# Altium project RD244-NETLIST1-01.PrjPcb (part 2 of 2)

## Sheet 6.SchDoc
size 609 x 444 mm
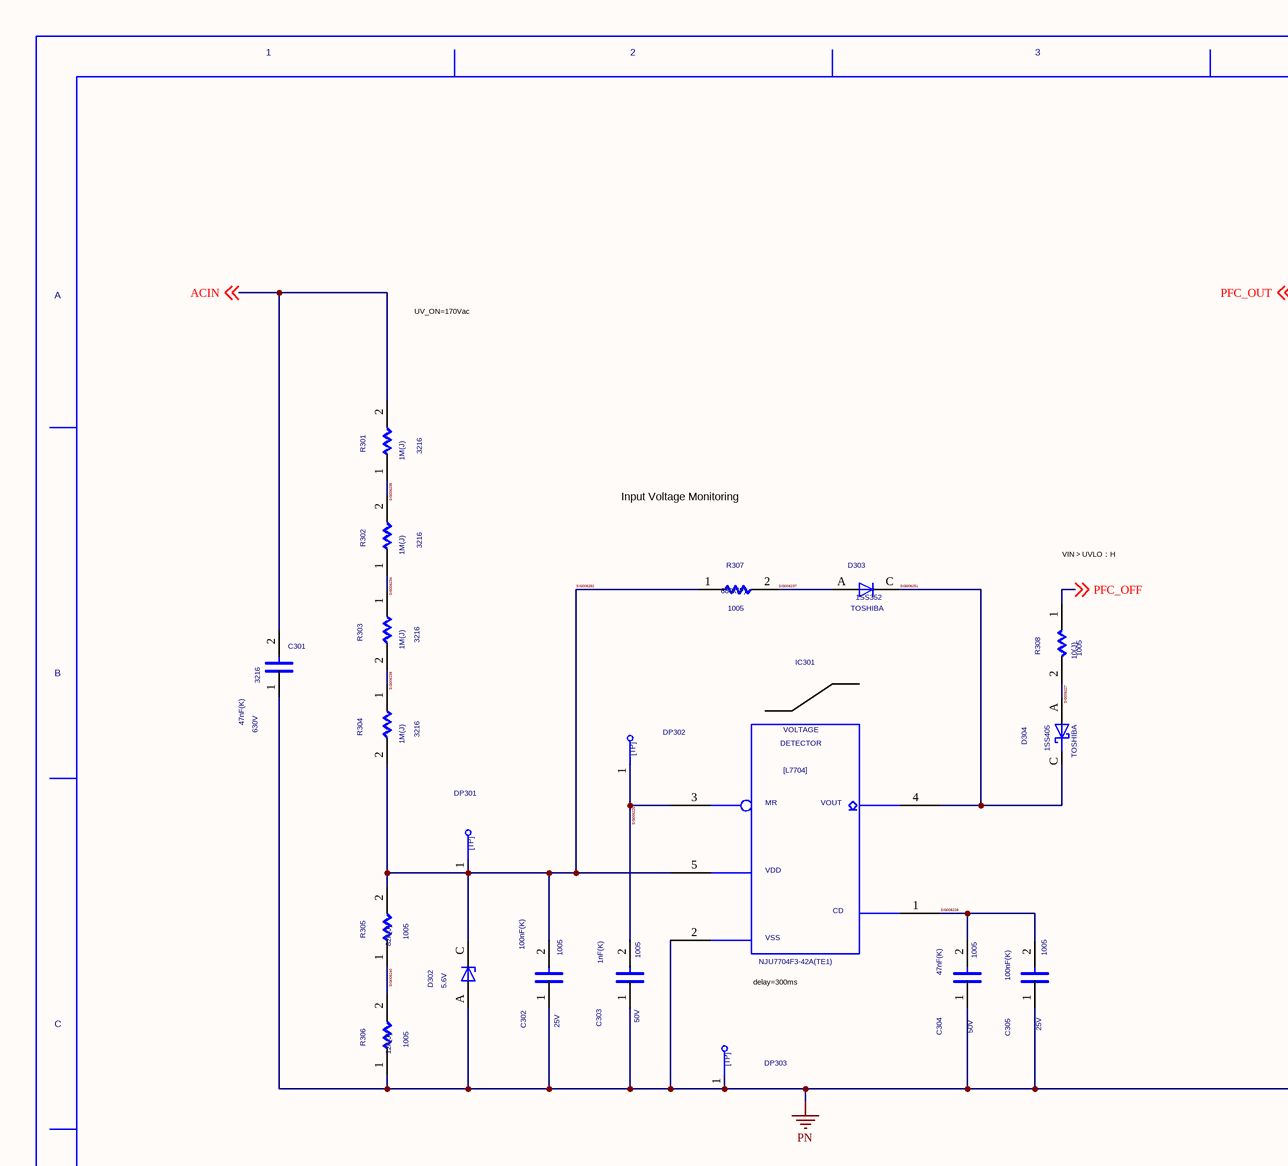
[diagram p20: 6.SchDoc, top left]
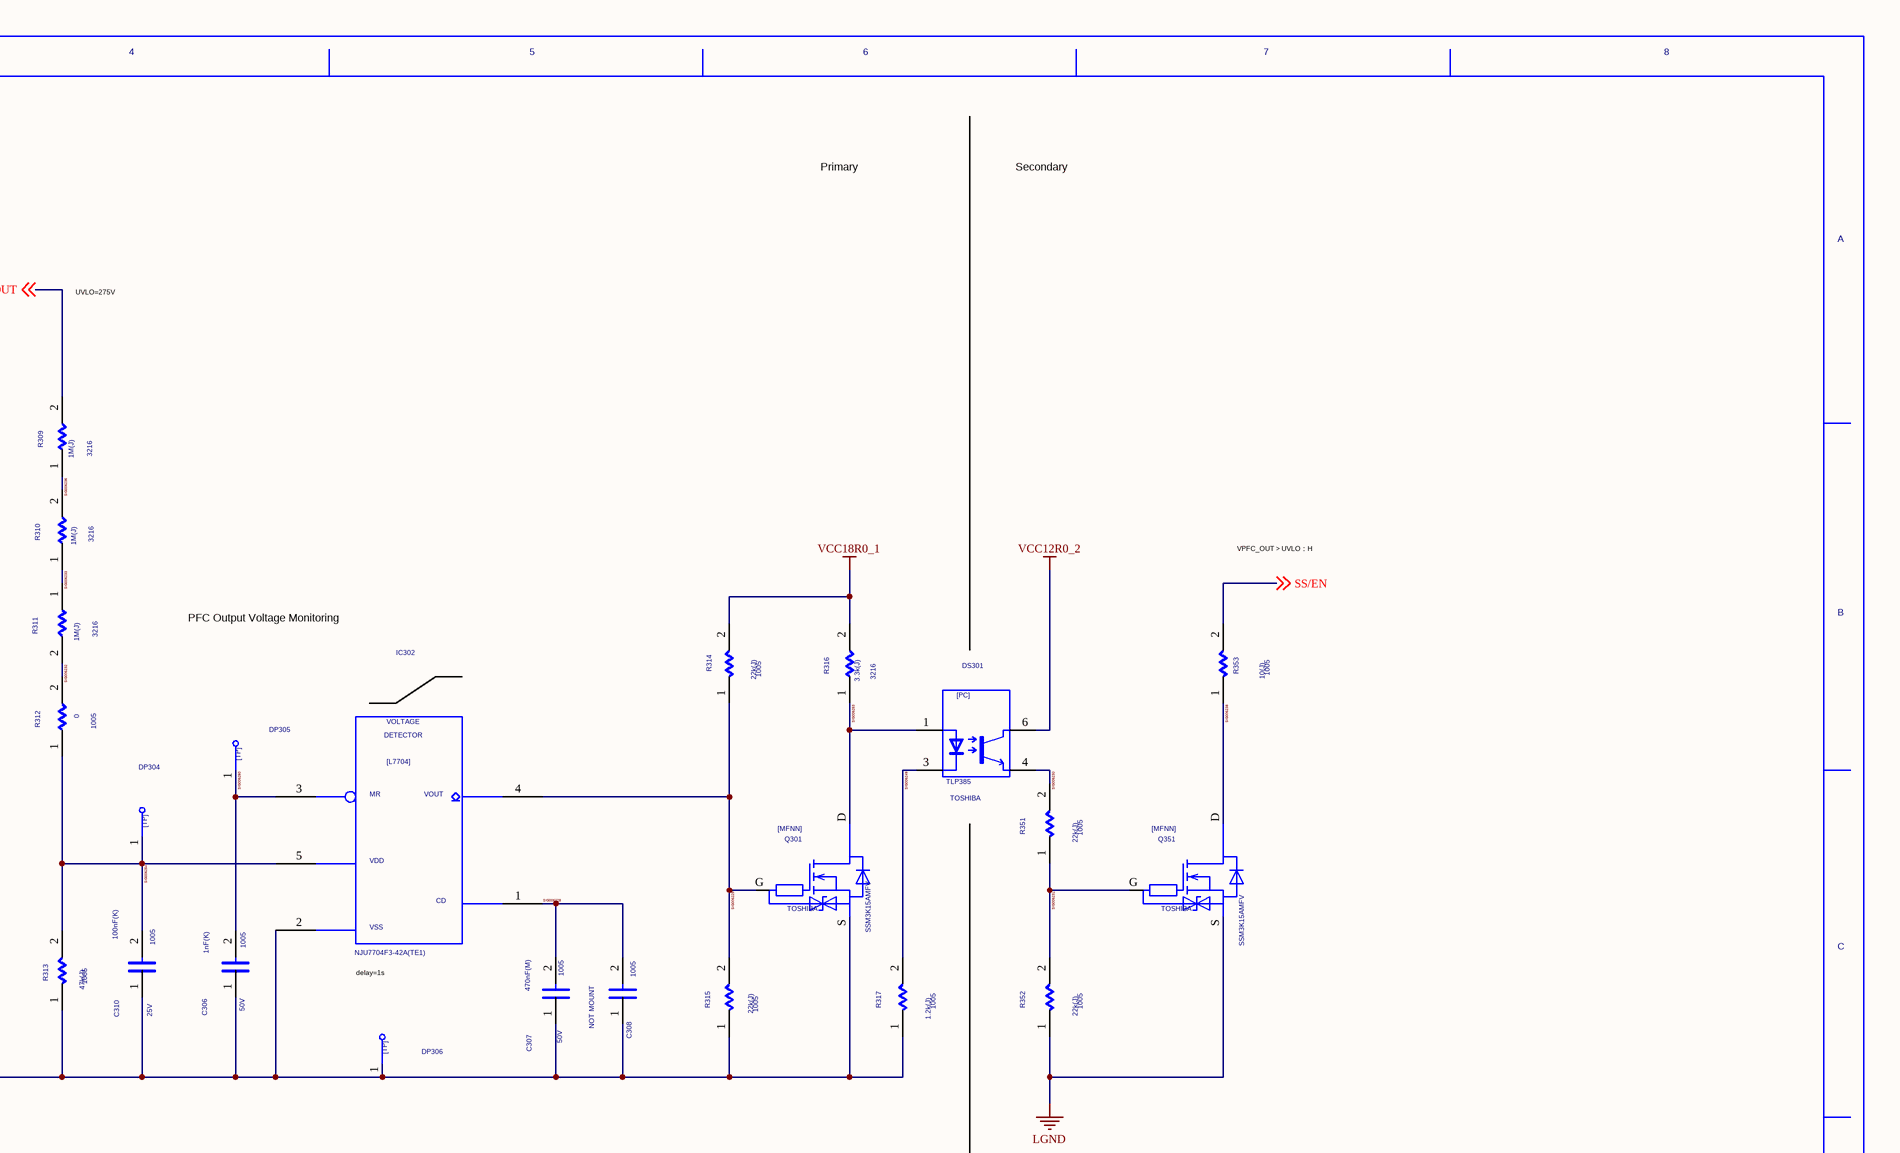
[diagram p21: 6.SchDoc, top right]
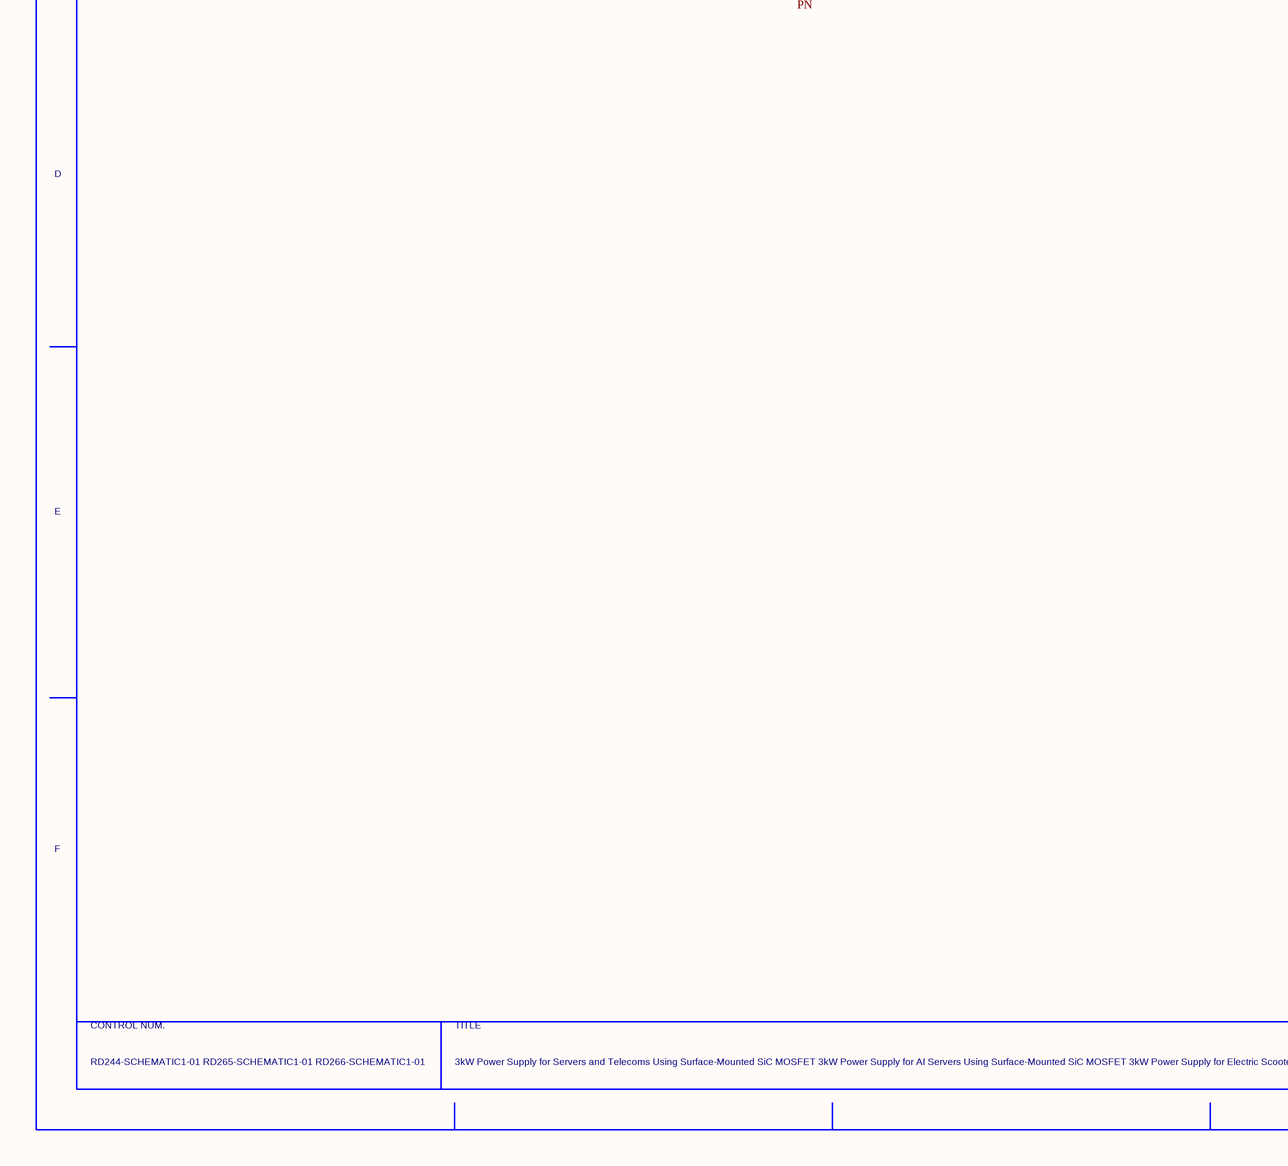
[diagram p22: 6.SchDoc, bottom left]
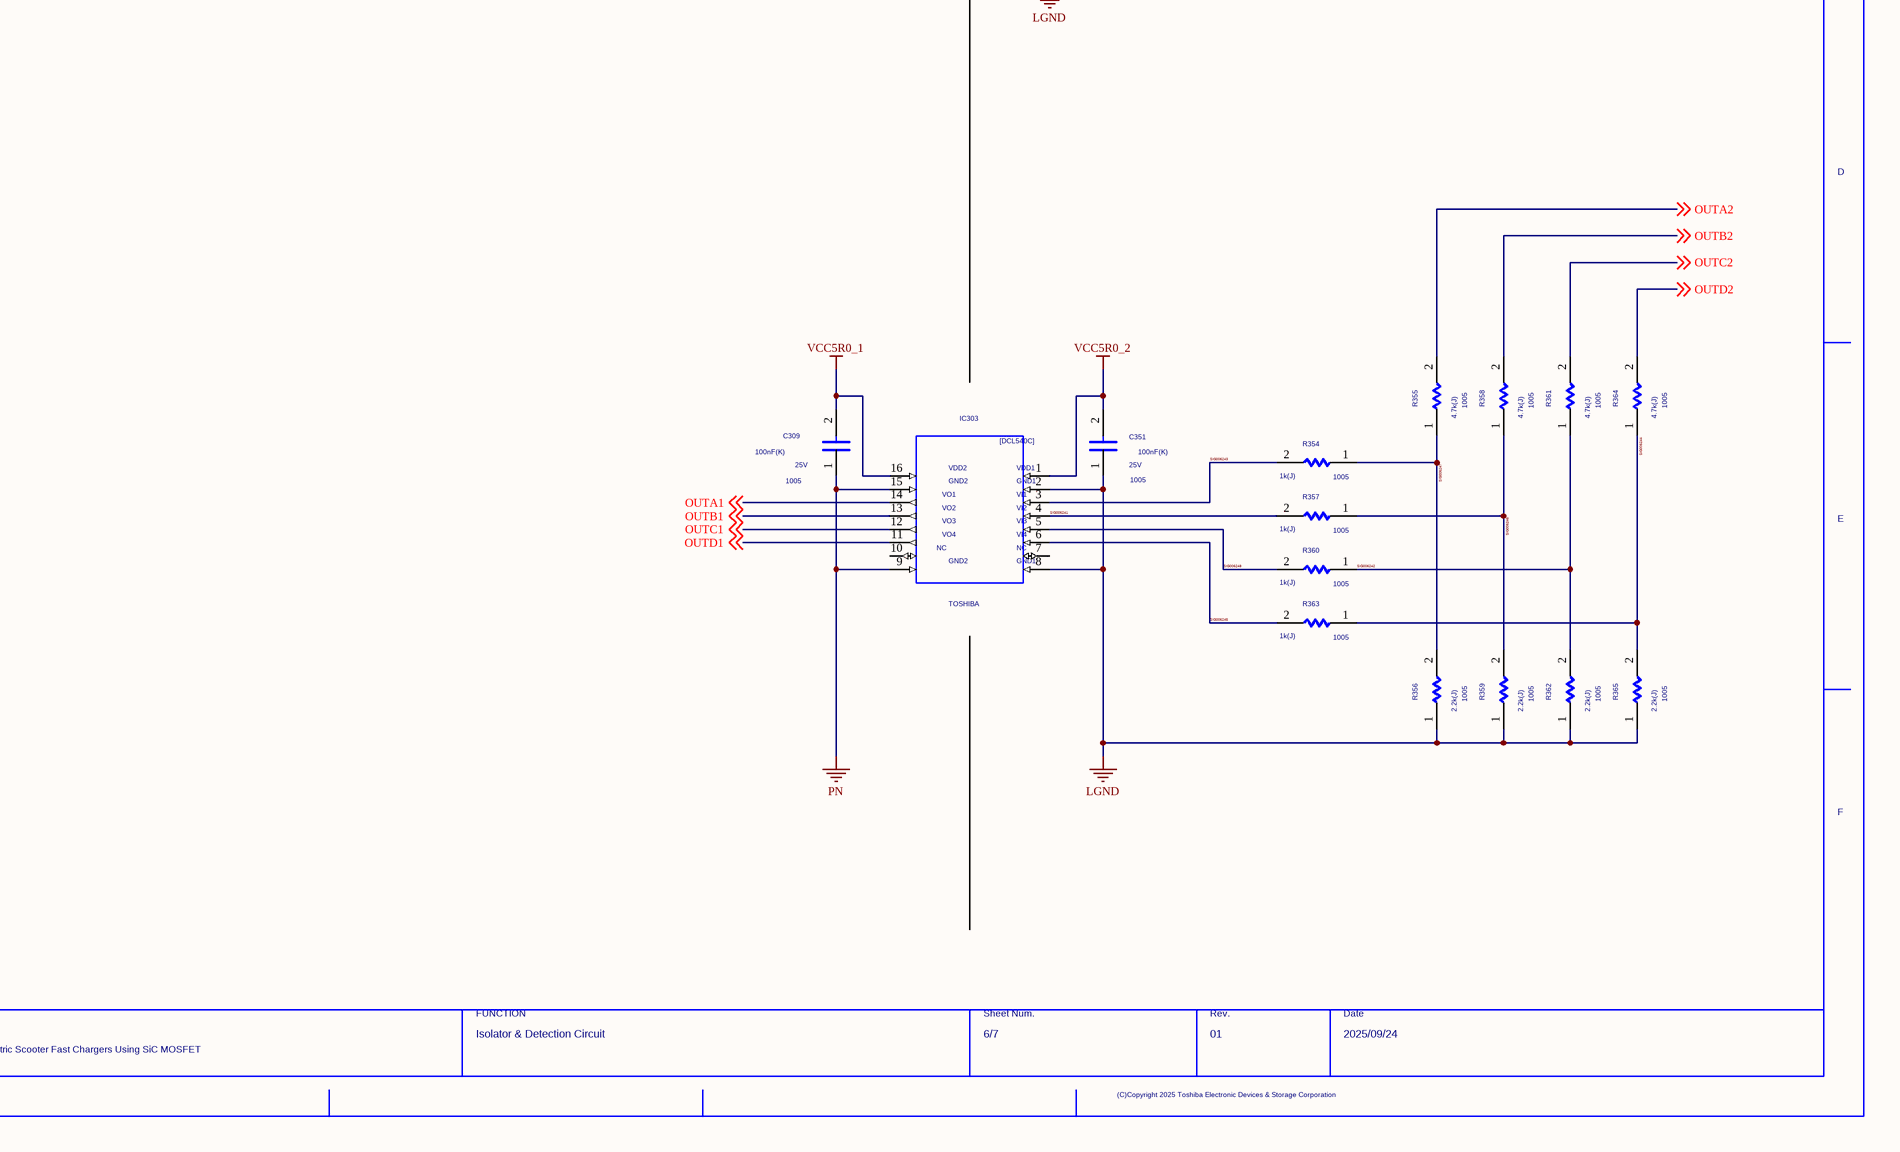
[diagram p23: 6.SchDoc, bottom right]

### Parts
(Parts that share a designator on the sheet are numbered #1, #2 ... from top to bottom, then left to right.)
C301  VAL1: 47nF(K)  VAL2: 630V  SIZECODESMD: 3216  (hidden comment: C)
C302  VAL1: 100nF(K)  VAL2: 25V  SIZECODESMD: 1005  (hidden comment: C)
C303  VAL1: 1nF(K)  VAL2: 50V  SIZECODESMD: 1005  (hidden comment: C)
C304  VAL1: 47nF(K)  VAL2: 50V  SIZECODESMD: 1005  (hidden comment: C)
C305  VAL1: 100nF(K)  VAL2: 25V  SIZECODESMD: 1005  (hidden comment: C)
C306  VAL1: 1nF(K)  VAL2: 50V  SIZECODESMD: 1005  (hidden comment: C)
C307  VAL1: 470nF(M)  VAL2: 50V  SIZECODESMD: 1005  (hidden comment: C)
C308  NOTMOUNT: NOT MOUNT  SIZECODESMD: 1005  (hidden comment: C)
C309  VAL1: 100nF(K)  VAL2: 25V  SIZECODESMD: 1005  (hidden comment: C)
C310  VAL1: 100nF(K)  VAL2: 25V  SIZECODESMD: 1005  (hidden comment: C)
C351  VAL1: 100nF(K)  VAL2: 25V  SIZECODESMD: 1005  (hidden comment: C)
D302  VAL1: 5.6V  (hidden comment: ZenerDiode_USC-01)
D303  USERCOMPTEXT3: TOSHIBA  VAL3: 1SS352  (hidden comment: D)
D304  USERCOMPTEXT3: TOSHIBA  (hidden comment: 1SS405)
DP301  TP  (value not drawn)
DP302  TP  (value not drawn)
DP303  TP  (value not drawn)
DP304  TP  (value not drawn)
DP305  TP  (value not drawn)
DP306  TP  (value not drawn)
DS301  USERCOMPTEXT3: TOSHIBA  (hidden comment: TLP385)
IC301  VAL3: NJU7704F3-42A(TE1)  (hidden comment: L7704)
IC302  VAL3: NJU7704F3-42A(TE1)  (hidden comment: L7704)
IC303  USERCOMPTEXT3: TOSHIBA  (hidden comment: DCL540C01)
Q301  USERCOMPTEXT3: TOSHIBA  VAL3: SSM3K15AMFV  (hidden comment: MFNN)
Q351  USERCOMPTEXT3: TOSHIBA  VAL3: SSM3K15AMFV  (hidden comment: MFNN)
R301  VAL1: 1M(J)  SIZECODESMD: 3216  (hidden comment: R)
R302  VAL1: 1M(J)  SIZECODESMD: 3216  (hidden comment: R)
R303  VAL1: 1M(J)  SIZECODESMD: 3216  (hidden comment: R)
R304  VAL1: 1M(J)  SIZECODESMD: 3216  (hidden comment: R)
R305  VAL1: 82k(J)  SIZECODESMD: 1005  (hidden comment: R)
R306  VAL1: 12k(J)  SIZECODESMD: 1005  (hidden comment: R)
R307  VAL1: 680k(F)  SIZECODESMD: 1005  (hidden comment: R)
R308  VAL1: 10(J)  SIZECODESMD: 1005  (hidden comment: R)
R309  VAL1: 1M(J)  SIZECODESMD: 3216  (hidden comment: R)
R310  VAL1: 1M(J)  SIZECODESMD: 3216  (hidden comment: R)
R311  VAL1: 1M(J)  SIZECODESMD: 3216  (hidden comment: R)
R312  VAL1: 0  SIZECODESMD: 1005  (hidden comment: R)
R313  VAL1: 47k(J)  SIZECODESMD: 1005  (hidden comment: R)
R314  VAL1: 22k(J)  SIZECODESMD: 1005  (hidden comment: R)
R315  VAL1: 22k(J)  SIZECODESMD: 1005  (hidden comment: R)
R316  VAL1: 3.3k(J)  SIZECODESMD: 3216  (hidden comment: R)
R317  VAL1: 1.2k(J)  SIZECODESMD: 1005  (hidden comment: R)
R351  VAL1: 22k(J)  SIZECODESMD: 1005  (hidden comment: R)
R352  VAL1: 22k(J)  SIZECODESMD: 1005  (hidden comment: R)
R353  VAL1: 10(J)  SIZECODESMD: 1005  (hidden comment: R)
R354  VAL1: 1k(J)  SIZECODESMD: 1005  (hidden comment: R)
R355  VAL1: 4.7k(J)  SIZECODESMD: 1005  (hidden comment: R)
R356  VAL1: 2.2k(J)  SIZECODESMD: 1005  (hidden comment: R)
R357  VAL1: 1k(J)  SIZECODESMD: 1005  (hidden comment: R)
R358  VAL1: 4.7k(J)  SIZECODESMD: 1005  (hidden comment: R)
R359  VAL1: 2.2k(J)  SIZECODESMD: 1005  (hidden comment: R)
R360  VAL1: 1k(J)  SIZECODESMD: 1005  (hidden comment: R)
R361  VAL1: 4.7k(J)  SIZECODESMD: 1005  (hidden comment: R)
R362  VAL1: 2.2k(J)  SIZECODESMD: 1005  (hidden comment: R)
R363  VAL1: 1k(J)  SIZECODESMD: 1005  (hidden comment: R)
R364  VAL1: 4.7k(J)  SIZECODESMD: 1005  (hidden comment: R)
R365  VAL1: 2.2k(J)  SIZECODESMD: 1005  (hidden comment: R)
U?#6  DATE: 2025/09/24  DRAWINGNUMBER: RD244-SCHEMATIC1-01 / RD265-SCHEMATIC1-01 / RD266-SCHEMATIC1-01  TITLE: 3kW Power Supply for Servers and Telecoms Using Surface-Mounted SiC MOSFET / 3kW Power Supply for AI Servers Using Surface-Mounted SiC MOSFET / 3kW Power Supply for Electric Scooter Fast Chargers Using SiC MOSFET  FUNCTION: Isolator & Detection Circuit  SHEETNUMBER: 6/7  REVISION: 01  (hidden comment: WAKU_DEF_A3_1)

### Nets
LGND: C351.1 IC303.2 IC303.8 Q351.S R352.1 R356.1 R359.1 R362.1 R365.1
PN: C301.1 C302.1 C303.1 C304.1 C305.1 C306.1 C307.1 C308.1 C309.1 C310.1 D302.A DP303.1 DP306.1 IC301.2 IC302.2 IC303.9 IC303.15 Q301.S R306.1 R313.1 R315.1 R317.1
VCC5R0_1: C309.2 IC303.16
VCC5R0_2: C351.2 IC303.1
VCC12R0_2: DS301.6
VCC18R0_1: R314.2 R316.2
ACIN: C301.2 R301.2 ; off-sheet ACIN
OUTA1: IC303.14 ; off-sheet OUTA1
OUTA2: R355.2 ; off-sheet OUTA2
OUTB1: IC303.13 ; off-sheet OUTB1
OUTB2: R358.2 ; off-sheet OUTB2
OUTC1: IC303.12 ; off-sheet OUTC1
OUTC2: R361.2 ; off-sheet OUTC2
OUTD1: IC303.11 ; off-sheet OUTD1
OUTD2: R364.2 ; off-sheet OUTD2
PFC_OFF: R308.1 ; off-sheet PFC_OFF
PFC_OUT: R309.2 ; off-sheet PFC_OUT
SIG006225: C303.2 DP302.1 IC301.3
SIG006226: C304.2 C305.2 IC301.1
SIG006227: D304.A R308.2
SIG006228: C307.2 C308.2 IC302.1
SIG006229: IC302.4 Q301.G R314.1 R315.2
SIG006230: DS301.4 R351.2
SIG006231: Q351.G R351.1 R352.2
SIG006232: R311.2 R312.2
SIG006233: R310.1 R311.1
SIG006234: R302.1 R303.1
SIG006235: R301.1 R302.2
SIG006236: R309.1 R310.2
SIG006237: D303.A R307.2
SIG006238: Q351.D R353.1
SIG006239: R303.2 R304.1
SIG006240: R305.1 R306.2
SIG006241: IC303.4 R357.2
SIG006242: R360.1 R361.1 R362.2
SIG006243: IC303.3 R354.2
SIG006244: R363.1 R364.1 R365.2
SIG006245: IC303.6 R363.2
SIG006246: R357.1 R358.1 R359.2
SIG006247: R354.1 R355.1 R356.2
SIG006248: IC303.5 R360.2
SIG006249: DS301.3 R317.2
SIG006250: C306.2 DP305.1 IC302.3
SIG006251: D303.C D304.C IC301.4
SIG006252: C302.2 D302.C DP301.1 IC301.5 R304.2 R305.2 R307.1
SIG006253: DS301.1 Q301.D R316.1
SIG006254: C310.2 DP304.1 IC302.5 R312.1 R313.2
SS/EN: R353.2 ; off-sheet SS/EN

Not connected (* = marked no-connect by the designer): IC303 7 10

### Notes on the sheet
- Primary
- Secondary
- UV_ON=170Vac
  UV_OFF=158Vac
- UVLO=275V
- Input Voltage Monitoring
- VIN＞UVLO：H
  VIN＜UVLO：L
- VPFC_OUT＞UVLO：H
  VPFC_OUT＜UVLO：L
- PFC Output Voltage Monitoring
- (near IC301) delay=300ms
- (near IC302) delay=1s

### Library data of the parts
C301 = C_Dup2: OriginalSymbolOrigin: (2540,7620); COMP: PRT_46; MAXGCOUNT: 1; SAVECOUNT: 0
C302 C305 C309 C310 C351 = C_Dup2: SQ_PART_MODEL: CON_100N; OriginalSymbolOrigin: (2540,7620); COMP: PRT_52; MAXGCOUNT: 1; ADSCNVFLAG: ON; ADSCOMPONENTNAME: C_1005; SAVECOUNT: 0
C303 C304 C306 C307 = C_Dup2: OriginalSymbolOrigin: (2540,7620); COMP: PRT_52; MAXGCOUNT: 1; SAVECOUNT: 0
C308 = C_Dup2: VAL1: 10nF(K); VAL2: 50V; OriginalSymbolOrigin: (2540,7620); COMP: PRT_52; MAXGCOUNT: 1; SAVECOUNT: 0
D302 = ZENERDIODE_USC-01: SAVEAREA0: -4630,-153,17114,13055; TIME: 14:49:55; UPDATEUSER: t4887876; UPDATETIME: 08:23:49; SAVECOUNT: 9; OriginalSymbolOrigin: (5080,5080); MAXGCOUNT: 1; ADSCNVFLAG: ON; ADSCOMPONENTNAME: D_ZD; VAL3: XCUZ5V6
D303 = D_Dup1: SAVEAREA0: -225,-91,12804,7836; SAVECOUNT: 3; TIME: 14:49:55; UPDATEUSER: 19870035; UPDATETIME: 14:20:16; VAL1: 1SS352(TPH3,F); OriginalSymbolOrigin: (5080,5080); USERCOMPTEXT2: 80V,0.1A; COMP: PRT_27
D304 = 1SS405: SAVEAREA0: -4630,-153,17114,13055; TIME: 14:49:55; UPDATEUSER: t4887876; UPDATETIME: 11:25:22; SAVECOUNT: 16; CHIPSET: SOD-523; VAL1: 20V; VAL2: 0.05A; OriginalSymbolOrigin: (5080,5080); MAXGCOUNT: 1; ADSCNVFLAG: ON; ADSCOMPONENTNAME: D_SBD
DP301-DP306 = TP: TIME: 16:12:21; UPDATEUSER: fukuda-y; UPDATETIME: 16:18:11; SAVECOUNT: 2; SAVEAREA0: -242,-92,12810,7836; OriginalSymbolOrigin: (0,7620); USERCOMPTEXT1: Φ1.5mm; COMP: DTP815
DS301 = TLP385: TIME: 18:37:26; UPDATEUSER: t4887876; UPDATETIME: 18:41:04; SAVECOUNT: 3; OriginalSymbolOrigin: (5080,17780); GATENO: 1; ADSCNVFLAG: ON
IC301 IC302 = L7704: SAVECOUNT: 23; SAVEAREA0: -14253,-557,65080,48696; TIME: 18:10:57; UPDATEUSER: 19990028; UPDATETIME: 10:41:32; OriginalSymbolOrigin: (7620,45720); MAXGCOUNT: 1; COMP: GDM470001845; ADSCNVFLAG: ON; VAL1: NJU7704F3-25A(TE1); FUNCTION: OTHER
IC303 = DCL540C01: TIME: 11:12:35; UPDATEUSER: t6860224; UPDATETIME: 18:45:42; SAVECOUNT: 6; SAVEAREA0: -81052,-32740,106905,52903; OriginalSymbolOrigin: (5080,27940); MAXGCOUNT: 1; FUNCTION: FXD
Q301 Q351 = MFNN: SAVECOUNT: 25; SAVEAREA0: -2884,-274,25430,18334; TIME: 08:01:03; UPDATEUSER: sato-yr; UPDATETIME: 13:42:20; VAL1: SSM3K15AMFV,L3F(T; OriginalSymbolOrigin: (2540,17780); MAXGCOUNT: 1; COMP: GDM410000663; ADSCNVFLAG: ON; ADSCOMPONENTNAME: Q_MFNN
R301-R304 R309-R311 = R_Dup2: VAL2: 250mW; OriginalSymbolOrigin: (5080,5080); COMP: PRT_5; CHIPSIZE: 1608; MAXGCOUNT: 1; SAVECOUNT: 0
R305-R308 R313-R315 R317 R351-R365 = R_Dup2: VAL2: 63mW; OriginalSymbolOrigin: (5080,5080); COMP: GDM010004481; CHIPSIZE: 1608; MAXGCOUNT: 1; SAVECOUNT: 0
R312 = R_Dup2: VAL2: 63mW; OriginalSymbolOrigin: (5080,5080); MAXGCOUNT: 1; COMP: GDM010004481; CHIPSIZE: 1608
R316 = R_Dup2: SQ_PART_MODEL: RES_4.87K; VAL2: 250mW; OriginalSymbolOrigin: (5080,5080); COMP: PRT_5; CHIPSIZE: 1608; MAXGCOUNT: 1; ADSCNVFLAG: ON; ADSCOMPONENTNAME: R_3216; SAVECOUNT: 0
U?#6 = WAKU_DEF_A3_1: PLOTTIME: HH:MM; SAVEAREA0: 96913,-567914,509243,-368858; TIME: 16:14:05; UPDATEUSER: t5459927; UPDATETIME: 13:12:48; SAVECOUNT: 3; ZONEOFFSETX: 36; ZONEOFFSETY: -24; OriginalSymbolOrigin: (12700,-12700); SHTSAVECOUNT: 262; PAGENUMBER: 6; DESIGNED: TOSHIBA

## Sheet 7.SchDoc
size 609 x 444 mm
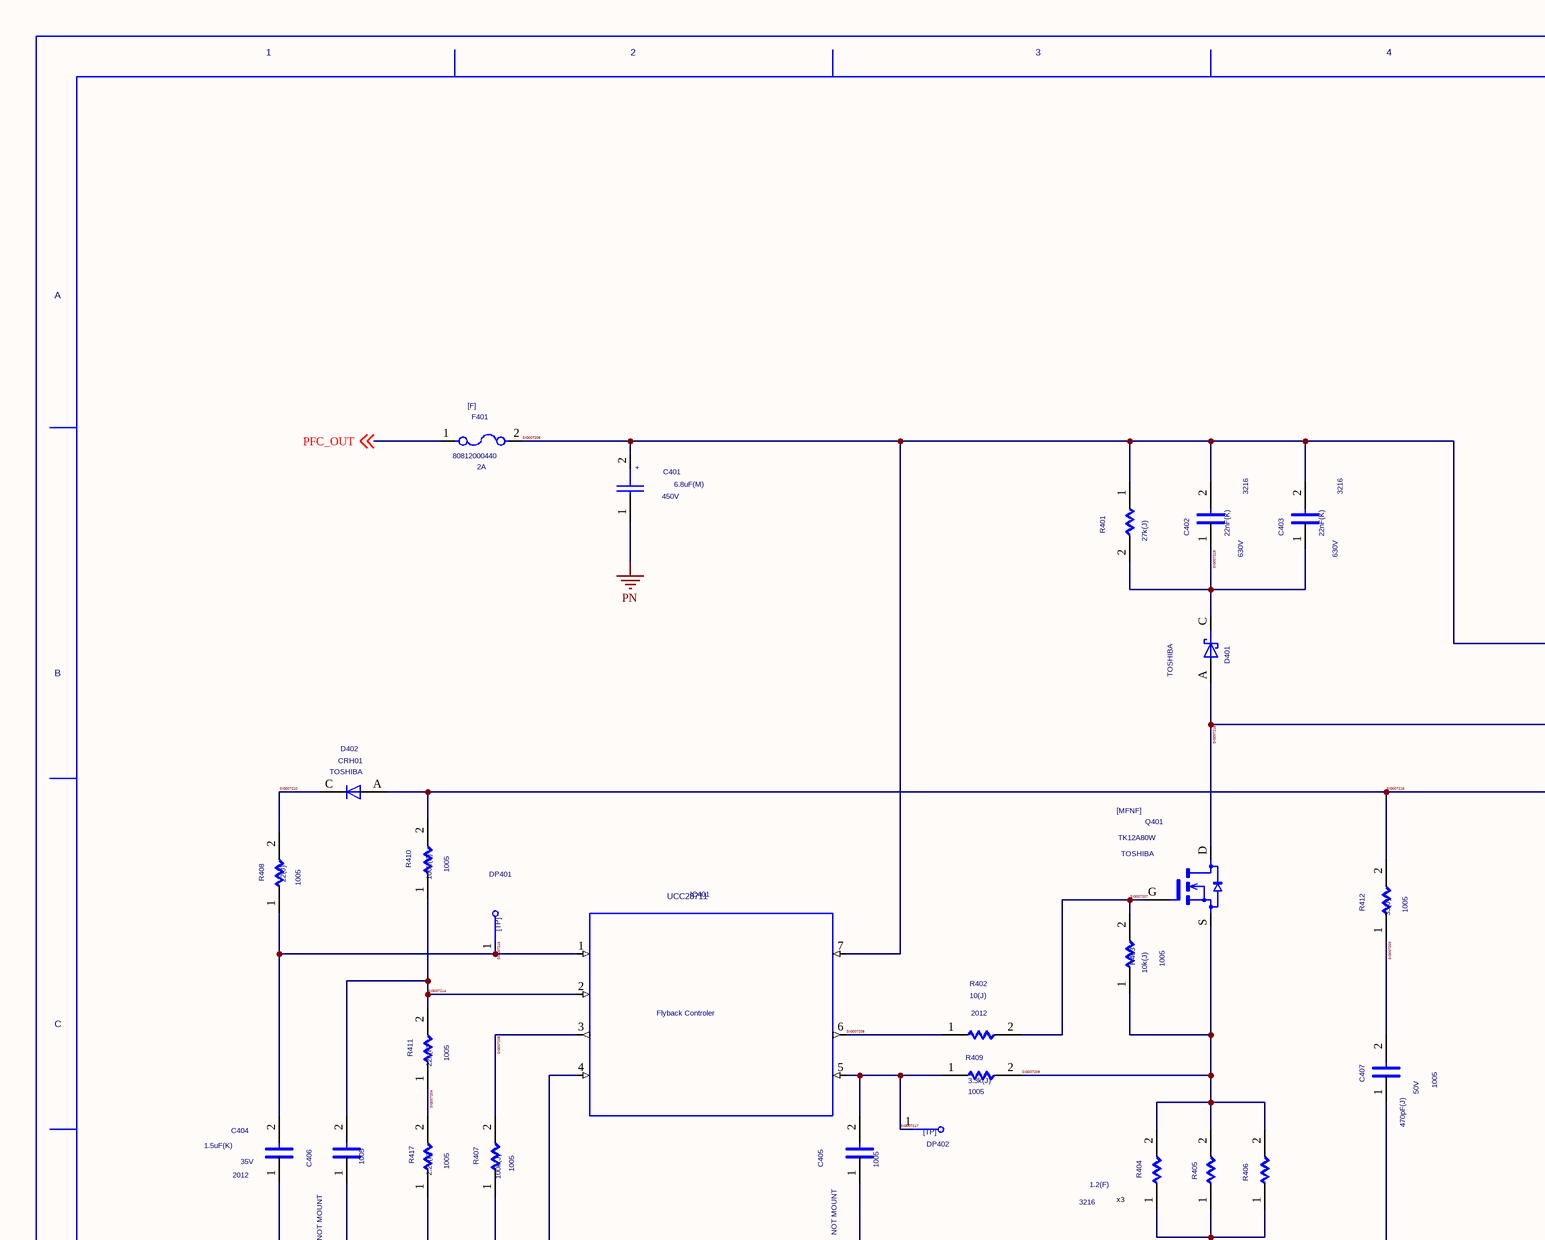
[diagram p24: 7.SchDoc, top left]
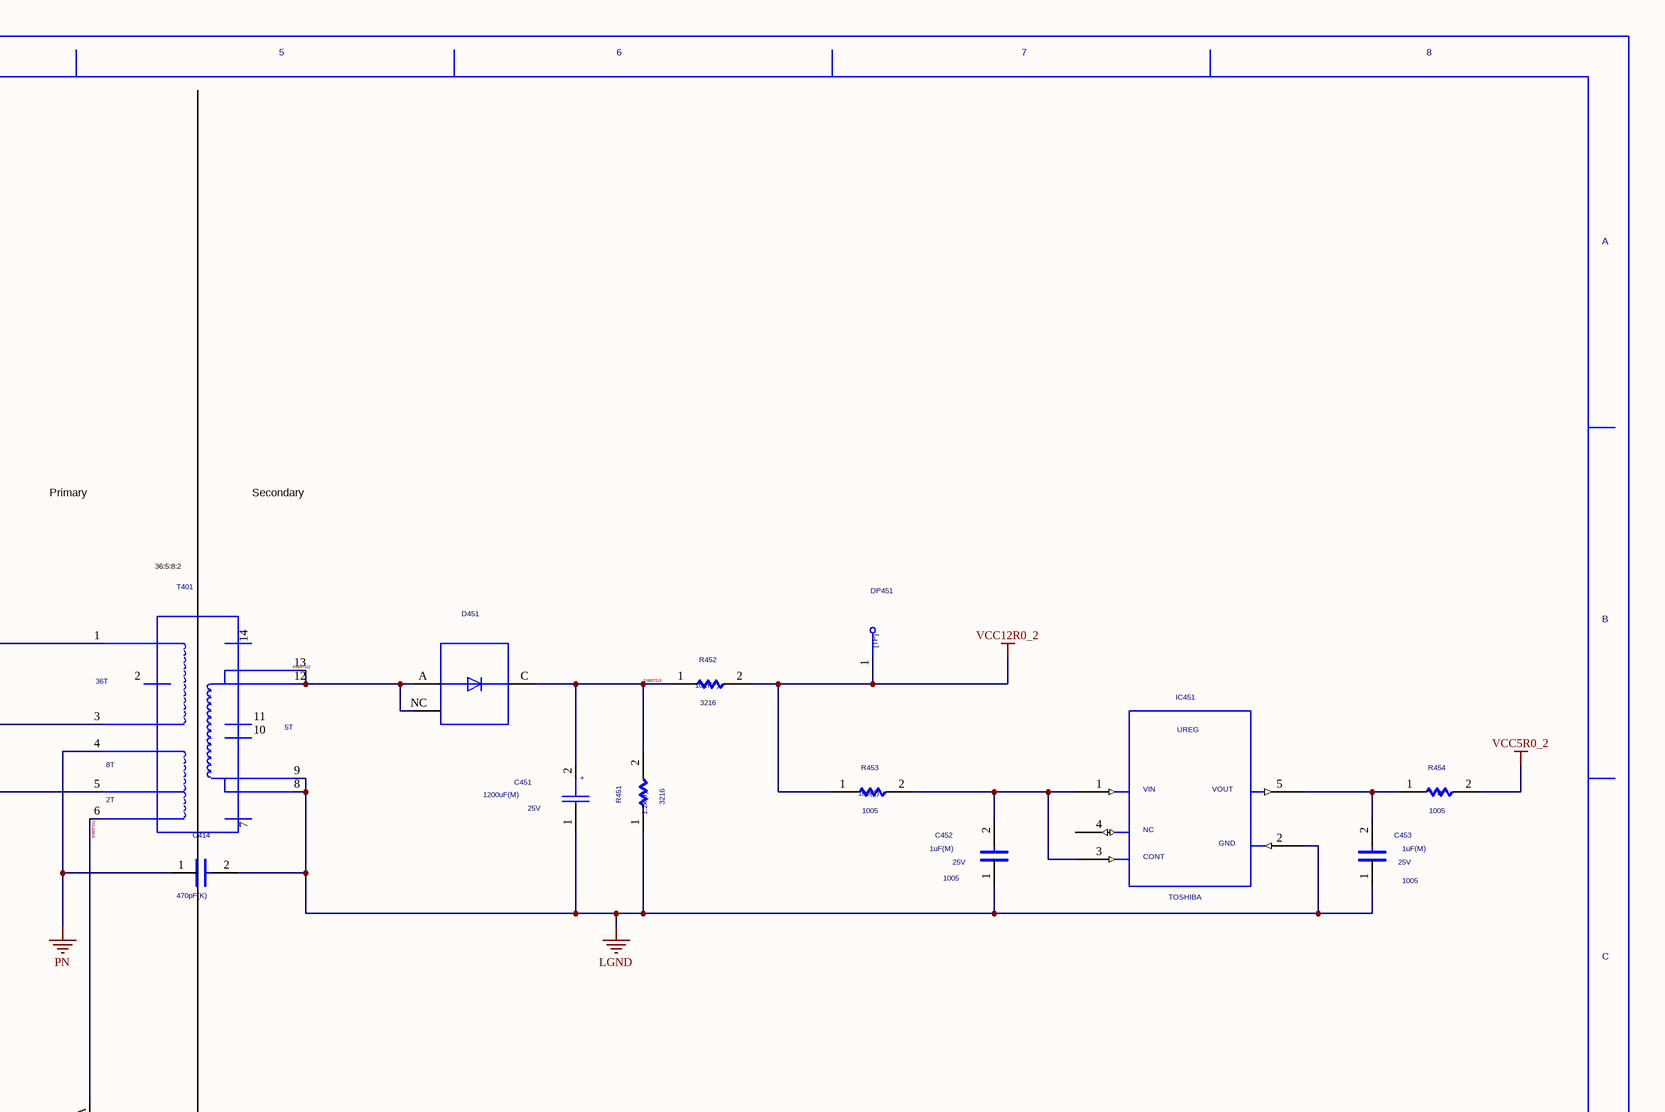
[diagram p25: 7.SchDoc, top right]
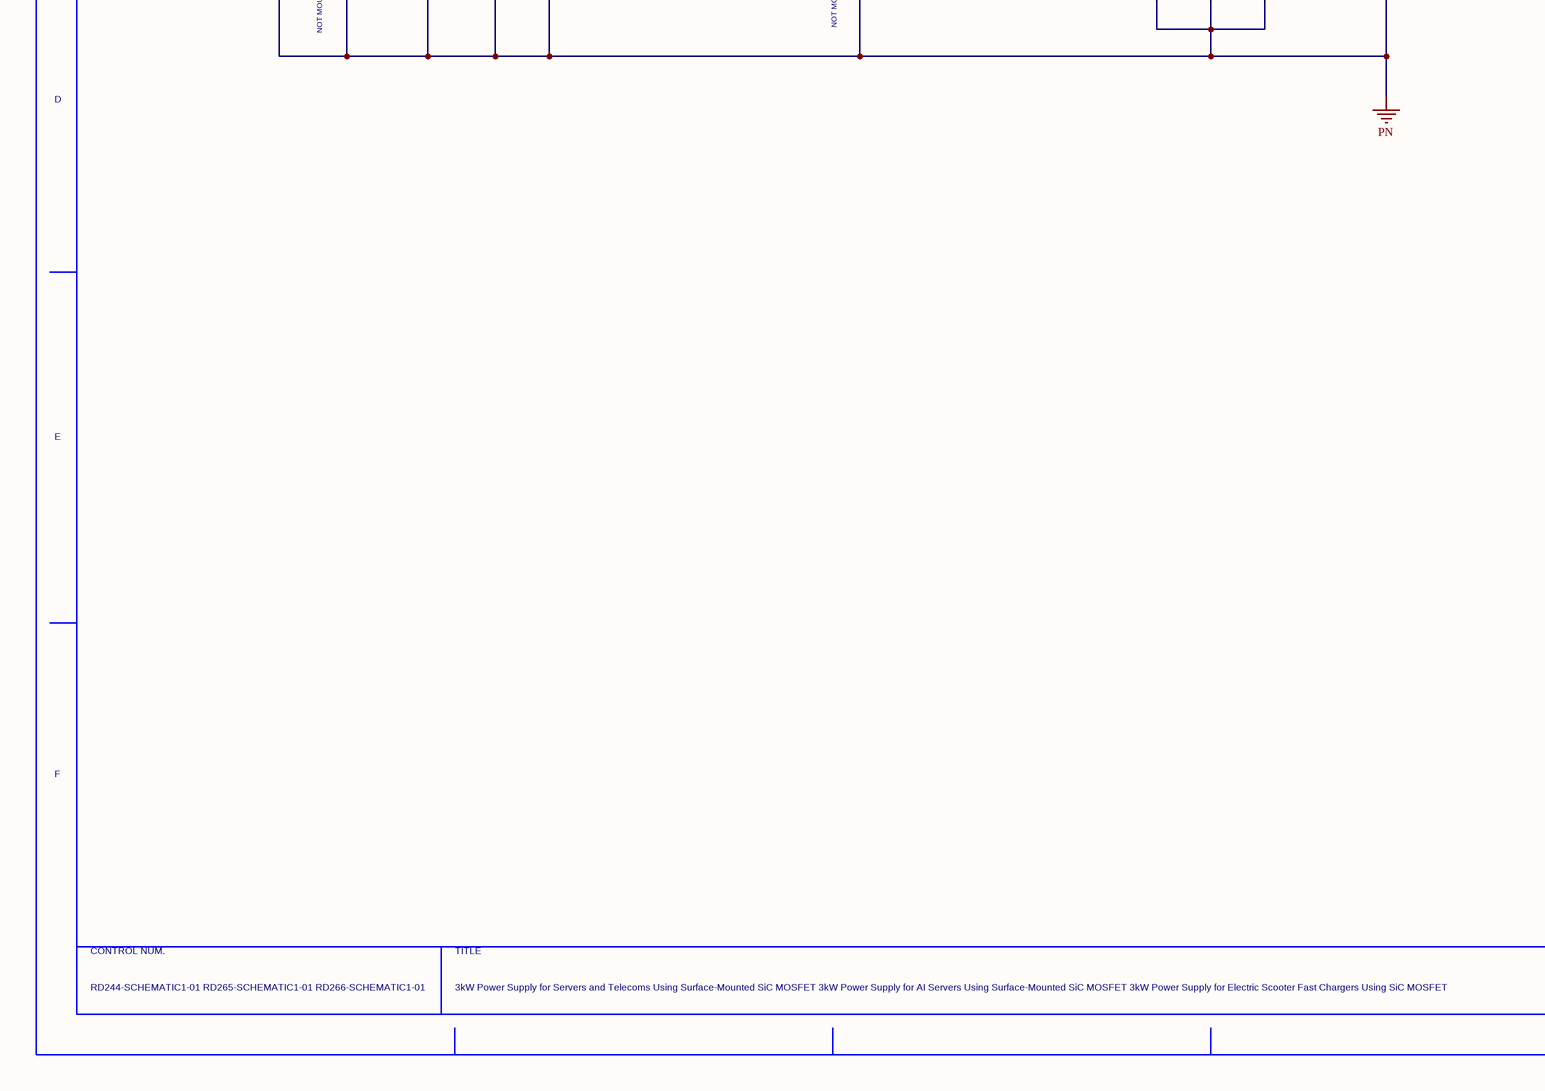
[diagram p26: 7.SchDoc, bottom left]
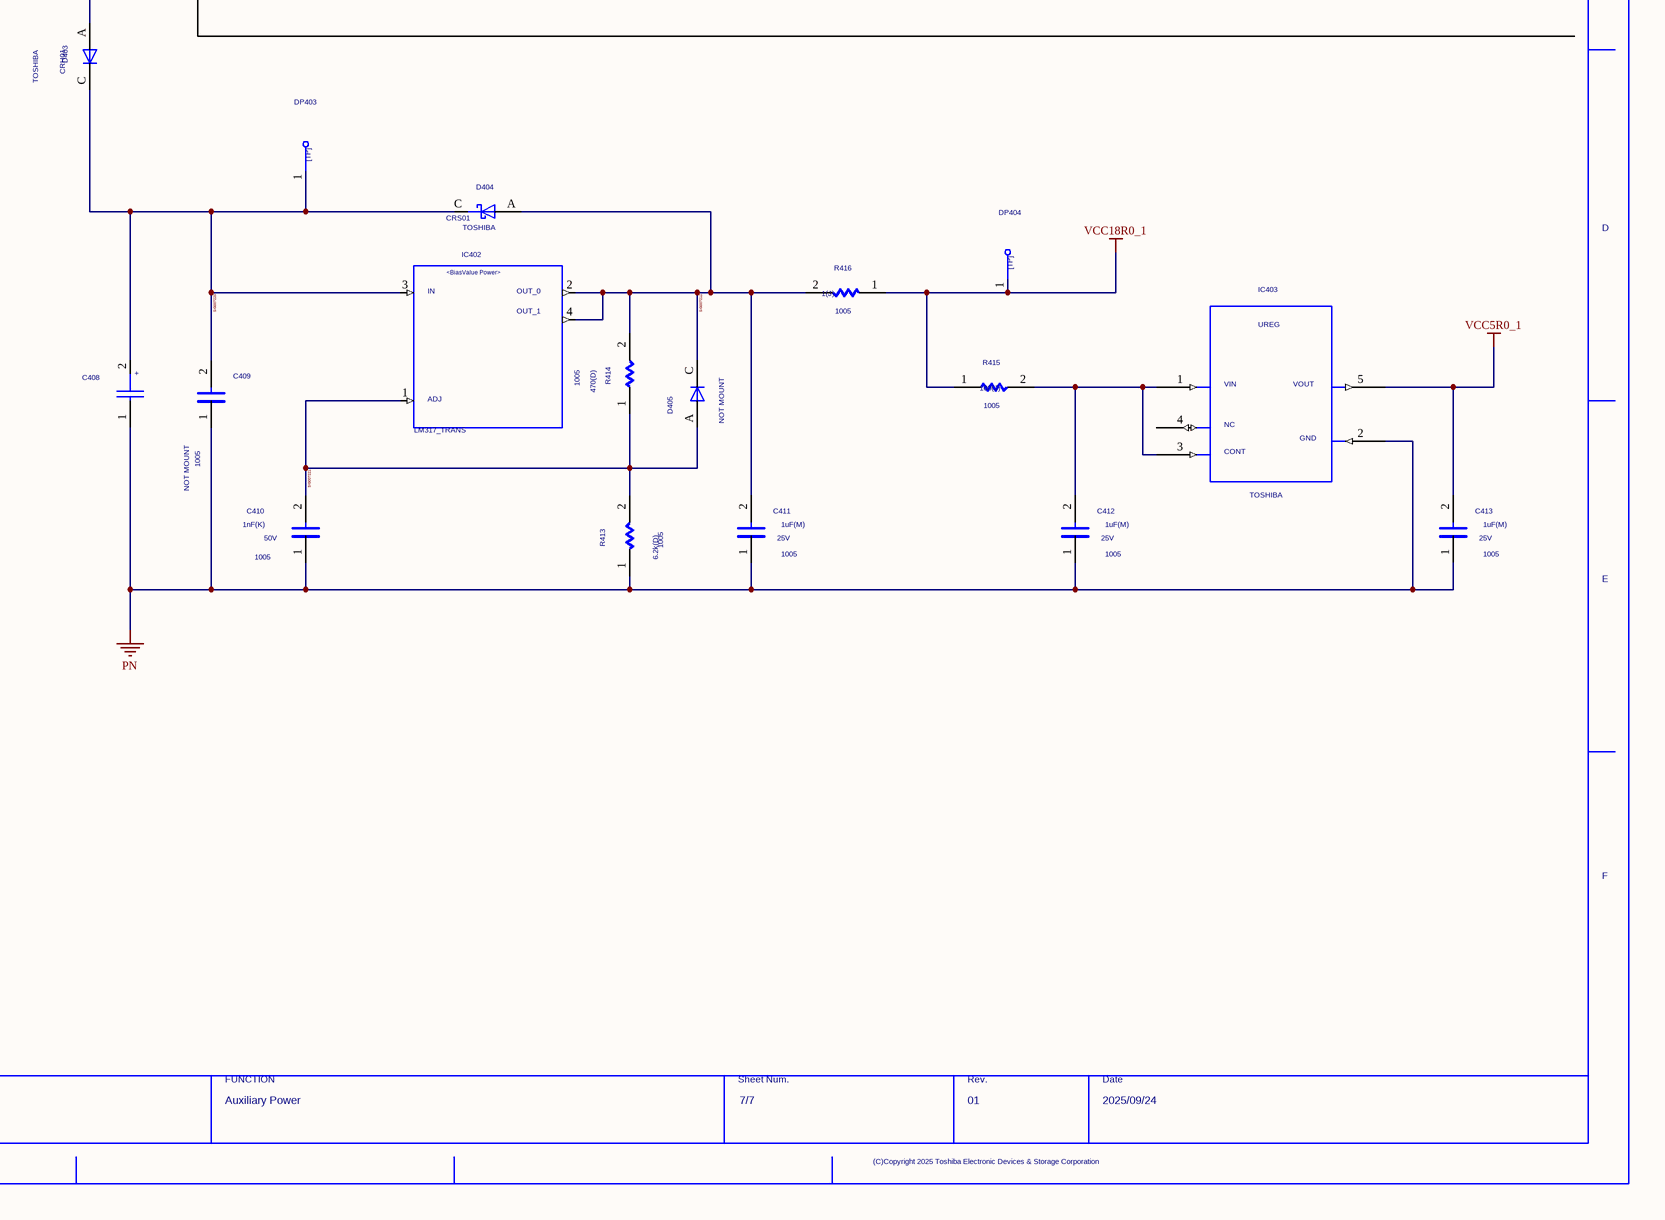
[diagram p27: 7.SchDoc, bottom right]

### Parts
(Parts that share a designator on the sheet are numbered #1, #2 ... from top to bottom, then left to right.)
C401  VAL1: 6.8uF(M)  VAL2: 450V  (hidden comment: CP)
C402  VAL1: 22nF(K)  VAL2: 630V  SIZECODESMD: 3216  (hidden comment: C)
C403  VAL1: 22nF(K)  VAL2: 630V  SIZECODESMD: 3216  (hidden comment: C)
C404  VAL1: 1.5uF(K)  VAL2: 35V  SIZECODESMD: 2012  (hidden comment: GRM21BC71E106KE01)
C405  NOTMOUNT: NOT MOUNT  SIZECODESMD: 1005  (hidden comment: C)
C406  NOTMOUNT: NOT MOUNT  SIZECODESMD: 1005  (hidden comment: C)
C407  VAL1: 470pF(J)  VAL2: 50V  SIZECODESMD: 1005  (hidden comment: C)
C408  EMLA350ARA331MJA0G  (value not drawn)
C409  NOTMOUNT: NOT MOUNT  SIZECODESMD: 1005  (hidden comment: C)
C410  VAL1: 1nF(K)  VAL2: 50V  SIZECODESMD: 1005  (hidden comment: C)
C411  VAL1: 1uF(M)  VAL2: 25V  SIZECODESMD: 1005  (hidden comment: C)
C412  VAL1: 1uF(M)  VAL2: 25V  SIZECODESMD: 1005  (hidden comment: C)
C413  VAL1: 1uF(M)  VAL2: 25V  SIZECODESMD: 1005  (hidden comment: C)
C414  USERCOMPTEXT1: 470pF(K)  (hidden comment: DE2B3SA221KA3BT02F)
C451  VAL1: 1200uF(M)  VAL2: 25V  (hidden comment: CP)
C452  VAL1: 1uF(M)  VAL2: 25V  SIZECODESMD: 1005  (hidden comment: C)
C453  VAL1: 1uF(M)  VAL2: 25V  SIZECODESMD: 1005  (hidden comment: C)
D401  USERCOMPTEXT3: TOSHIBA  (hidden comment: CRF03A)
D402  VAL1: CRH01  USERCOMPTEXT3: TOSHIBA  (hidden comment: D)
D403  VAL1: CRH01  USERCOMPTEXT3: TOSHIBA  (hidden comment: D)
D404  VAL1: CRS01  USERCOMPTEXT3: TOSHIBA  (hidden comment: SBD)
D405  NOTMOUNT: NOT MOUNT  (hidden comment: D)
D451  RF501BGE2S  (value not drawn)
DP401  TP  (value not drawn)
DP402  TP  (value not drawn)
DP403  TP  (value not drawn)
DP404  TP  (value not drawn)
DP451  TP  (value not drawn)
F401  VAL1: 2A  VAL3: 80812000440  (hidden comment: F)
IC401  UCC28711
IC402  LM317_TRANS  [DCY0004A_N]
IC403  USERCOMPTEXT3: TOSHIBA  (hidden comment: TCR1HF50B)
IC451  USERCOMPTEXT3: TOSHIBA  (hidden comment: TCR1HF50B)
Q401  USERCOMPTEXT3: TOSHIBA  VAL3: TK12A80W  (hidden comment: MFNF)
R401  VAL1: 27k(J)  (hidden comment: R)
R402  VAL1: 10(J)  SIZECODESMD: 2012  (hidden comment: R)
R403  VAL1: 10k(J)  SIZECODESMD: 1005  (hidden comment: R)
R404  VAL1: 1.2(F)  SIZECODESMD: 3216  (hidden comment: R)
R405  R  (value not drawn)
R406  R  (value not drawn)
R407  VAL1: 100k(J)  SIZECODESMD: 1005  (hidden comment: R)
R408  VAL1: 22(J)  SIZECODESMD: 1005  (hidden comment: R)
R409  VAL1: 3.3k(J)  SIZECODESMD: 1005  (hidden comment: R)
R410  VAL1: 100k(F)  SIZECODESMD: 1005  (hidden comment: R)
R411  VAL1: 22k(F)  SIZECODESMD: 1005  (hidden comment: R)
R412  VAL1: 33(J)  SIZECODESMD: 1005  (hidden comment: R)
R413  VAL1: 6.2k(D)  SIZECODESMD: 1005  (hidden comment: R)
R414  VAL1: 470(D)  SIZECODESMD: 1005  (hidden comment: R)
R415  VAL1: 100(J)  SIZECODESMD: 1005  (hidden comment: R)
R416  VAL1: 1(J)  SIZECODESMD: 1005  (hidden comment: R)
R417  VAL1: 2.2k(F)  SIZECODESMD: 1005  (hidden comment: R)
R451  VAL1: 1.2k(J)  SIZECODESMD: 3216  (hidden comment: R)
R452  VAL1: 10m(F)  SIZECODESMD: 3216  (hidden comment: R)
R453  VAL1: 100(J)  SIZECODESMD: 1005  (hidden comment: R)
R454  VAL1: 0  SIZECODESMD: 1005  (hidden comment: R)
T401  T3_12V67A  (value not drawn)
U?#7  DATE: 2025/09/24  DRAWINGNUMBER: RD244-SCHEMATIC1-01 / RD265-SCHEMATIC1-01 / RD266-SCHEMATIC1-01  TITLE: 3kW Power Supply for Servers and Telecoms Using Surface-Mounted SiC MOSFET / 3kW Power Supply for AI Servers Using Surface-Mounted SiC MOSFET / 3kW Power Supply for Electric Scooter Fast Chargers Using SiC MOSFET  FUNCTION: Auxiliary Power  SHEETNUMBER: 7/7  REVISION: 01  (hidden comment: WAKU_DEF_A3_1)

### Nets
LGND: C414.2 C451.1 C452.1 C453.1 IC451.2 R451.1 T401.8 T401.9
PN: C401.1 C404.1 C405.1 C406.1 C407.1 C408.1 C409.1 C410.1 C411.1 C412.1 C413.1 C414.1 IC401.4 IC403.2 R404.1 R405.1 R406.1 R407.1 R413.1 R417.1 T401.4
VCC5R0_1: C413.2 IC403.5
VCC5R0_2: R454.2
VCC12R0_2: DP451.1 R452.2 R453.1
VCC18R0_1: DP404.1 R415.1 R416.1
PFC_OUT: F401.1 ; off-sheet PFC_OUT
SIG007201: C453.2 IC451.5 R454.1
SIG007202: C452.2 IC451.1 IC451.3 R453.2
SIG007203: C407.2 R412.1
SIG007204: R411.1 R417.2
SIG007205: IC401.3 R407.2
SIG007206: C401.2 C402.2 C403.2 F401.2 IC401.7 R401.1 T401.1
SIG007207: Q401.G R402.2 R403.2
SIG007208: IC401.6 R402.1
SIG007209: Q401.S R403.1 R404.2 R405.2 R406.2 R409.2
SIG007210: D402.C R408.2
SIG007211: D403.A T401.6
SIG007212: C411.2 D404.A D405.C IC402.2 IC402.4 R414.2 R416.2
SIG007213: C451.2 D451.C R451.2 R452.1
SIG007214: C406.2 IC401.2 R410.1 R411.2
SIG007215: C404.2 DP401.1 IC401.1 R408.1
SIG007216: D402.A R410.2 R412.2 T401.5
SIG007217: C405.2 DP402.1 IC401.5 R409.1
SIG007218: D401.A Q401.D T401.3
SIG007219: C402.1 C403.1 D401.C R401.2
SIG007220: C408.2 C409.2 D403.C D404.C DP403.1 IC402.3
SIG007221: C410.2 D405.A IC402.1 R413.2 R414.1
SIG007222: D451.A D451.NC T401.12 T401.13
SIG008125: C412.2 IC403.1 IC403.3 R415.2

Not connected (* = marked no-connect by the designer): IC403 4; IC451 4; T401 2 7 10 11 14

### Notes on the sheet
- Primary
- Secondary
- 36:5:8:2
- (near R404) x3

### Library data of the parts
C401 C451 = CP: SAVEAREA0: -1450,-153,20294,13055; SAVECOUNT: 52; TIME: 15:02:55; UPDATEUSER: fukuda-y; UPDATETIME: 16:13:42; OriginalSymbolOrigin: (2540,10160); SIZECODESMD: DIP; COMP: PRT_3
C402 C403 = C_Dup1: OriginalSymbolOrigin: (2540,7620); COMP: PRT_46; SAVECOUNT: 0
C404 = GRM21BC71E106KE01: TIME: 10:25:11; UPDATEUSER: t4887876; UPDATETIME: 16:23:00; SAVECOUNT: 11; MAKER: Murata; OriginalSymbolOrigin: (2540,7620); CHIPSIZE: 1005; MAXGCOUNT: 1
C405 C406 = C_Dup2: VAL1: 150pF(J); VAL2: 50V; OriginalSymbolOrigin: (2540,7620); COMP: PRT_52; SAVECOUNT: 0
C407 C410 = C_Dup2: OriginalSymbolOrigin: (2540,7620); COMP: PRT_52; SAVECOUNT: 0
C408 = EMLA350ARA331MJA0G: SAVEAREA0: -1450,-153,20294,13055; SAVECOUNT: 53; TIME: 15:02:55; UPDATEUSER: t6860224; UPDATETIME: 18:00:37; VAL1: 330uF(M); VAL2: 35V; OriginalSymbolOrigin: (2540,10160); MAXGCOUNT: 1; SIZECODESMD: 1010
C409 = C_Dup2: VAL1: 2.2nF(K); VAL2: 50V; OriginalSymbolOrigin: (2540,7620); COMP: PRT_52; SAVECOUNT: 0
C411-C413 C452 C453 = C_Dup2: SQ_PART_MODEL: CON_1U; OriginalSymbolOrigin: (2540,7620); COMP: PRT_52; MAXGCOUNT: 1; ADSCNVFLAG: ON; ADSCOMPONENTNAME: C_1608; SAVECOUNT: 0
C414 = DE2B3SA221KA3BT02F: VAL1: 220pF(K); VAL2: 250V; TIME: 18:06:26; UPDATEUSER: t6860224; SAVECOUNT: 1; OriginalSymbolOrigin: (2540,7620); SIZECODESMD: DIP
D401 = CRF03A: SAVEAREA0: -4630,-153,17114,13055; TIME: 14:49:55; UPDATEUSER: t4887876; UPDATETIME: 15:42:51; SAVECOUNT: 12; MAXV: 600V; MAXI: 0.7A; OriginalSymbolOrigin: (5080,5080); USERCOMPTEXT2: 600V,0.7A; MAXGCOUNT: 1
D402 D403 = D: SAVEAREA0: -225,-91,12804,7836; SAVECOUNT: 3; TIME: 14:49:55; UPDATEUSER: 19870035; UPDATETIME: 14:20:16; OriginalSymbolOrigin: (5080,5080); USERCOMPTEXT2: 200V,1A; MAXGCOUNT: 1; ADSCNVFLAG: ON; ADSCOMPONENTNAME: D_D; COMP: GDM420000387
D404 = SBD: SAVEAREA0: -4630,-153,17114,13055; TIME: 14:49:55; UPDATEUSER: fukuda-y; UPDATETIME: 08:16:22; SAVECOUNT: 9; OriginalSymbolOrigin: (5080,5080); USERCOMPTEXT2: 30V,1A; MAXGCOUNT: 1; COMP: K4200730; ADSCNVFLAG: ON; ADSCOMPONENTNAME: D_SBD
D405 = D_Dup1: SAVEAREA0: -225,-91,12804,7836; SAVECOUNT: 3; TIME: 14:49:55; UPDATEUSER: 19870035; UPDATETIME: 14:20:16; OriginalSymbolOrigin: (5080,5080); USERCOMPTEXT2: 100V,0.25A; USERCOMPTEXT3: TOSHIBA; COMP: PRT_26; VAL3: BAS316; MAXGCOUNT: 1
D451 = RF501BGE2S: SAVEAREA0: -4931,-287,27399,20979; TIME: 08:58:08; UPDATEUSER: t4887876; UPDATETIME: 11:52:14; SAVECOUNT: 7; VAL1: 200V; VAL2: 5A; CHIPSET: TO-252GE; OriginalSymbolOrigin: (5080,17780)
DP401-DP404 DP451 = TP: as DP301-DP306 on sheet 6
F401 = F: OriginalSymbolOrigin: (2540,5080); COMP: 808****0440_LF; SAVECOUNT: 0
IC401 = UCC28711DR: PSPICETEMPLATE: X^@REFDES %CS %VS %CBC %DRV %VDD %GND %HV @MODEL; TIME: 16:40:05; UPDATEUSER: t4887876; UPDATETIME: 09:12:44; SAVECOUNT: 14; SAVEAREA0: -40606,-13411,99691,50516; OriginalSymbolOrigin: (2540,38100)
IC402 = LM317MDCY: ALTERNATE PARTNUMBER: LM317DCY; PARTNUMBER: LM317DCYR; MANUFACTURER: Texas Instruments; PIN_COUNT: 4; SYMBOLCREATER: Altium; DEVICESINPACKAGE: 1; ISHETEROGENEOUS: False; DEVICEDESIGNATOR: A; DEVICENUMBERING: Alpha; PSPICETEMPLATE: X^@REFDES %IN %ADJ %OUT_0 %OUT_1 @MODEL; ORIGINALSYMBOLORIGIN: (2540,30480); COMPTYPE: IC; TIME: 16:40:05; UPDATEUSER: t6860224; UPDATETIME: 16:01:55; SAVECOUNT: 6; SAVEAREA0: -16909,0,49982,30480; FUNCTION: FXD
IC403 IC451 = TCR1HF50B: SAVEAREA0: -444,-3509,43701,41525; TIME: 18:31:00; UPDATEUSER: t6860224; UPDATETIME: 18:26:20; SAVECOUNT: 17; VAL1: Linear Regulator; OriginalSymbolOrigin: (7620,35560)
Q401 = MFNF: SAVECOUNT: 11; SAVEAREA0: -7027,-292,21786,15988; OriginalSymbolOrigin: (5080,12700); COMP: K4100860
R401 = R: VAL2: 3W; OriginalSymbolOrigin: (5080,5080); COMP: PRT_54; SIZECODESMD: TH; SAVECOUNT: 0
R402 = R: VAL2: 250mW; OriginalSymbolOrigin: (5080,5080); COMP: R2012; SAVECOUNT: 0
R403 R407 R408 R410-R412 R417 = R: VAL2: 63mW; OriginalSymbolOrigin: (5080,5080); MAXGCOUNT: 1; COMP: GDM010004481; SAVECOUNT: 0
R404 R451 = R: VAL2: 250mW; OriginalSymbolOrigin: (5080,5080); COMP: PRT_5; SAVECOUNT: 0
R405 R406 = R: VAL2: 250mW; VAL1: 1.2(F); OriginalSymbolOrigin: (5080,5080); COMP: PRT_5; SIZECODESMD: 3216; SAVECOUNT: 0
R409 = R: VAL2: 63mW; OriginalSymbolOrigin: (5080,5080); COMP: GDM010004481; SAVECOUNT: 0
R413 R414 = R_Dup2: VAL2: 63mW; OriginalSymbolOrigin: (5080,5080); MAXGCOUNT: 1; COMP: GDM010004481; SAVECOUNT: 0
R415 R453 = R_Dup2: as R305-R308 on sheet 6
R416 = R_Dup2: SQ_PART_MODEL: RES_0; VAL2: 63mW; OriginalSymbolOrigin: (5080,5080); COMP: GDM010004481; CHIPSIZE: 1608; MAXGCOUNT: 1; ADSCNVFLAG: ON; ADSCOMPONENTNAME: R_1005; SAVECOUNT: 0
R452 = R: VAL2: 1W; OriginalSymbolOrigin: (5080,5080); COMP: PRT_5; SAVECOUNT: 0
R454 = R_Dup2: SQ_PART_MODEL: RES_0; VAL2: 63mW; OriginalSymbolOrigin: (5080,5080); COMP: GDM010004481; CHIPSIZE: 1608; MAXGCOUNT: 1; ADSCNVFLAG: ON; ADSCOMPONENTNAME: R_1005
T401 = TAM-PQ20-36-5: UPDATEUSER: t4887876; UPDATETIME: 19:22:14; SAVECOUNT: 21; TIME: 16:40:06; SAVEAREA0: -85659,-25353,110804,64166; ORIGINALSYMBOLORIGIN: (0,40640); VAL1: 36:8:2:5
U?#7 = WAKU_DEF_A3_1: PLOTTIME: HH:MM; SAVEAREA0: 96913,-567914,509243,-368858; TIME: 18:12:27; UPDATEUSER: t5459927; UPDATETIME: 13:12:48; SAVECOUNT: 20; ZONEOFFSETX: 36; ZONEOFFSETY: -24; OriginalSymbolOrigin: (12700,-12700); PAGENUMBER: 7; NOTMOUNT: MOUNT; SHTSAVECOUNT: 218

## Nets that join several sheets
FG: 1 (8 pins), 5 (C507.1 C509.2 R505.1 R506.1)
LGND: 3 (75 pins), 4 (21 pins), 5 (17 pins), 6 (9 pins), 7 (8 pins)
PN: 1 (C11.1 C54.1 D2.A RY1.1), 2 (33 pins), 3 (6 pins), 6 (22 pins), 7 (21 pins)
VCC5R0_1: 6 (C309.2 IC303.16), 7 (C413.2 IC403.5)
VCC5R0_2: 6 (C351.2 IC303.1), 7 (R454.2)
VCC12R0_2: 3 (R151.1 R201.1), 4 (R256.1), 5 (CN501.1 CN501.2), 6 (DS301.6), 7 (DP451.1 R452.2 R453.1)
VCC18R0_1: 1 (D1.C), 2 (A51.3 R64.1), 3 (A101.3 A102.3), 6 (R314.2 R316.2), 7 (DP404.1 R415.1 R416.1)
AC-L: 1 (C9.2 R4.2 RY1.3 RY1.6), 2 (D51.A D53.A D55.2 L51.1)
AC-N: 1 (C8.2 C9.1 L2.4), 2 (D52.A D54.A D55.3 L52.1)
ACIN: 2 (D51.C D52.C), 6 (C301.2 R301.2)
CS: 3 (D251.C), 4 (R273.2 R274.2 R275.2 R276.2)
OUTA1: 3 (A101.1), 6 (IC303.14)
OUTA2: 4 (DP252.1 IC251.22), 6 (R355.2)
OUTB1: 3 (A101.2), 6 (IC303.13)
OUTB2: 4 (DP253.1 IC251.21), 6 (R358.2)
OUTC1: 3 (A102.1), 6 (IC303.12)
OUTC2: 4 (DP254.1 IC251.20), 6 (R361.2)
OUTD1: 3 (A102.2), 6 (IC303.11)
OUTD2: 4 (DP255.1 IC251.19), 6 (R364.2)
OUTE: 3 (IC151.2 IC201.2), 4 (DP256.1 IC251.18)
OUTF: 3 (IC151.4 IC201.4), 4 (DP257.1 IC251.17)
PFC_OFF: 2 (C59.2 DP51.1 IC51.18), 6 (R308.1)
PFC_OUT: 2 (7 pins), 3 (R101.2 T101.2), 6 (R309.2), 7 (F401.1)
PSFB_OUT: 3 (13 pins), 4 (R279.2), 5 (22 pins)
SS/EN: 4 (C251.2 DP251.1 IC251.5), 6 (R353.2)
